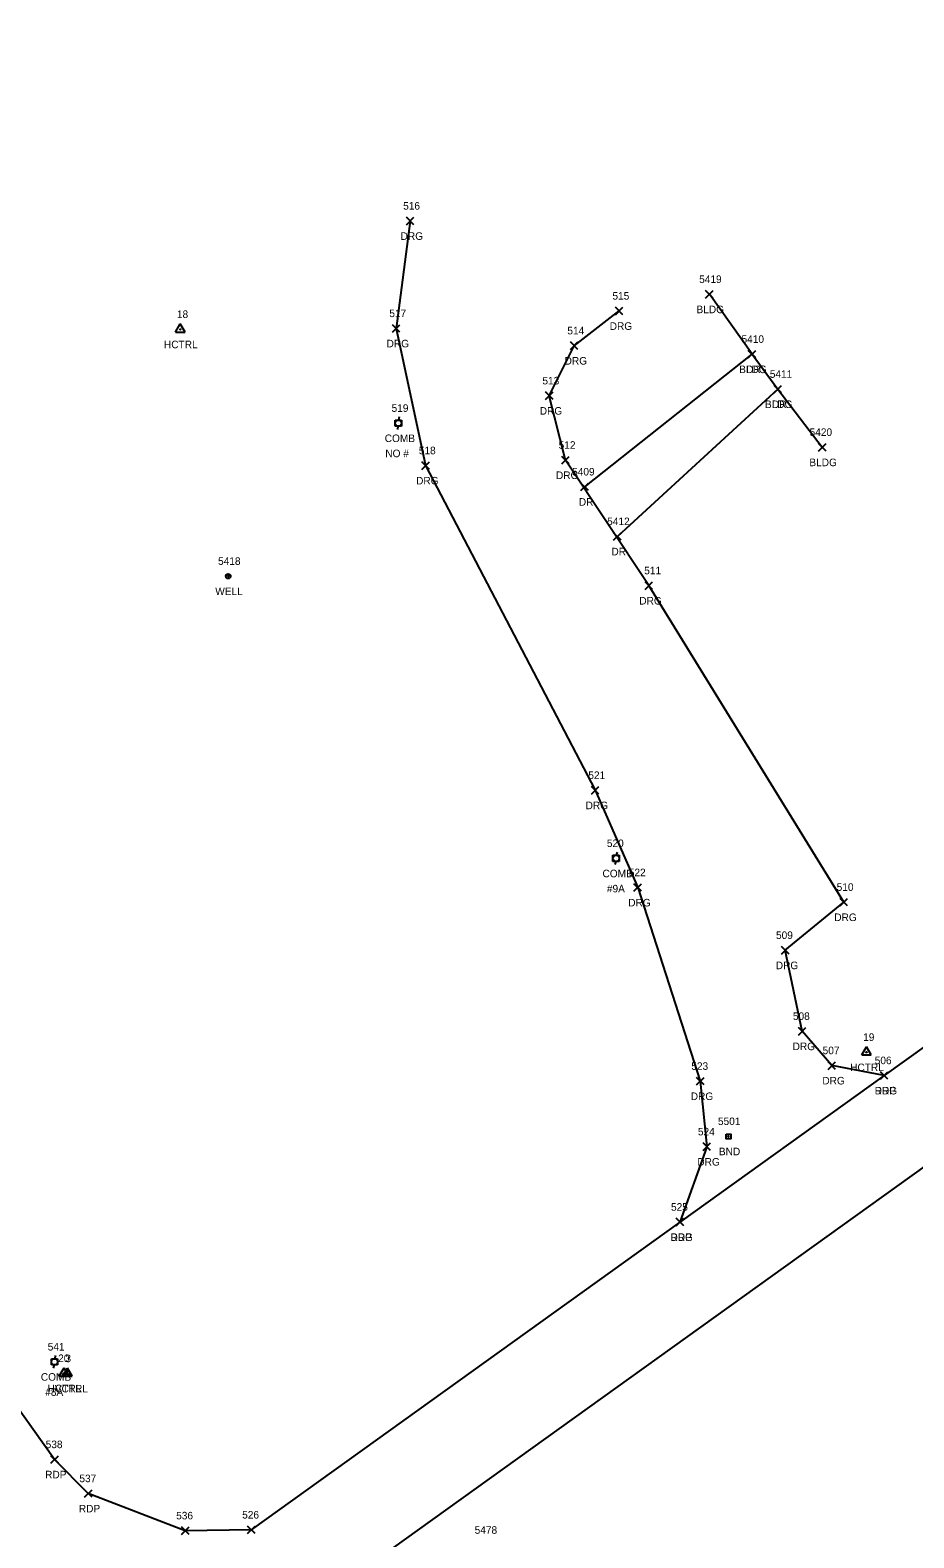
# Model space of a CAD drawing. Extents: x 1481523 to 1489083, y 884156 to 893756.
# Drawn here: x 1487626 to 1487859.9, y 886406.2 to 886805.3 of the extents above; entities that cross this region are included whole.
import ezdxf

# ---------------------------------------------------------------- set-up
doc = ezdxf.new("R2010")
doc.units = 0
for name, color, linetype in [('C_A', 7, 'Continuous'), ('C_I', 7, 'Continuous'), ('CPH', 7, 'Continuous'), ('CPSM', 7, 'Continuous'), ('L_A', 7, 'Continuous'), ('L_I', 7, 'Continuous'), ('L_TIC', 7, 'Continuous'), ('LBC', 7, 'Continuous'), ('Level 18', 7, 'Continuous'), ('M_A', 7, 'Continuous'), ('M_I', 7, 'Continuous'), ('P_A', 7, 'Continuous'), ('P_I', 7, 'Continuous'), ('P_TIC', 7, 'Continuous'), ('PET', 7, 'Continuous'), ('R_A', 7, 'Continuous'), ('R_I', 7, 'Continuous'), ('R_TIC', 7, 'Continuous'), ('RDG', 7, 'Continuous'), ('RDP', 7, 'Continuous'), ('U_A', 7, 'Continuous'), ('U_C', 7, 'Continuous'), ('U_I', 7, 'Continuous'), ('UP', 7, 'Continuous'), ('UWW', 7, 'Continuous')]:
    doc.layers.add(name, color=color, linetype=linetype)

msp = doc.modelspace()

# ---------------------------------------------------------------- linework, layer by layer
at = {"layer": 'CPH'}
for p, q in [((1487664.49, 886725.41), (1487665.74, 886727.57)), ((1487664.49, 886725.41), (1487666.99, 886725.41)), ((1487666.99, 886725.41), (1487665.74, 886727.57)), ((1487665.74, 886726.13), (1487665.74, 886726.13)), ((1487846.13, 886534.02), (1487847.38, 886536.19)), ((1487848.63, 886534.02), (1487847.38, 886536.19)), ((1487846.13, 886534.02), (1487848.63, 886534.02)), ((1487847.38, 886534.74), (1487847.38, 886534.74)), ((1487633.7, 886449.01), (1487634.95, 886451.17)), ((1487633.7, 886449.01), (1487636.2, 886449.01)), ((1487636.2, 886449.01), (1487634.95, 886451.17)), ((1487634.95, 886449.73), (1487634.95, 886449.73))]:
    msp.add_line(p, q, dxfattribs=at)
for centre in [(1487665.74, 886726.13), (1487847.38, 886534.74), (1487634.95, 886449.73)]:
    msp.add_circle(centre, 0.0833, dxfattribs=at)
at = {"layer": 'CPSM'}
for p, q in [((1487634.65, 886448.97), (1487635.9, 886451.13)), ((1487634.65, 886448.97), (1487635.9, 886449.69)), ((1487634.65, 886448.97), (1487637.15, 886448.97)), ((1487637.15, 886448.97), (1487635.9, 886451.13)), ((1487635.9, 886449.69), (1487635.9, 886451.13)), ((1487635.9, 886449.69), (1487635.9, 886449.69)), ((1487635.9, 886449.69), (1487637.15, 886448.97))]:
    msp.add_line(p, q, dxfattribs=at)
at = {"layer": 'L_TIC'}
for points in [[(1487804.78, 886734.41), (1487806.78, 886736.41)], [(1487806.78, 886734.41), (1487804.78, 886736.41)], [(1487816.07, 886718.55), (1487818.07, 886720.55)], [(1487818.07, 886718.55), (1487816.07, 886720.55)], [(1487816.07, 886718.55), (1487818.07, 886720.55)], [(1487818.07, 886718.55), (1487816.07, 886720.55)], [(1487822.91, 886709.3), (1487824.91, 886711.3)], [(1487824.91, 886709.3), (1487822.91, 886711.3)], [(1487834.66, 886693.91), (1487836.66, 886695.91)], [(1487836.66, 886693.91), (1487834.66, 886695.91)]]:
    msp.add_lwpolyline(points, dxfattribs=at)
at = {"layer": 'LBC'}
for points in [[(1487817.07, 886719.55), (1487805.78, 886735.41)], [(1487817.07, 886719.55), (1487823.91, 886710.3), (1487835.66, 886694.91)]]:
    msp.add_lwpolyline(points, dxfattribs=at)
at = {"layer": 'Level 18'}
msp.add_lwpolyline([(1487810.19, 886513.09), (1487811.44, 886513.09), (1487811.44, 886511.84), (1487810.19, 886511.84)], close=True, dxfattribs=at)
msp.add_circle((1487810.82, 886512.47), 0.0833, dxfattribs=at)
at = {"layer": 'P_TIC'}
for points in [[(1487851.05, 886527.58), (1487853.05, 886529.58)], [(1487853.05, 886527.58), (1487851.05, 886529.58)], [(1487796.99, 886488.79), (1487798.99, 886490.79)], [(1487798.99, 886488.79), (1487796.99, 886490.79)], [(1487631.47, 886425.93), (1487633.47, 886427.93)], [(1487633.47, 886425.93), (1487631.47, 886427.93)], [(1487640.38, 886416.92), (1487642.38, 886418.92)], [(1487642.38, 886416.92), (1487640.38, 886418.92)], [(1487666.06, 886407.07), (1487668.06, 886409.07)], [(1487668.06, 886407.07), (1487666.06, 886409.07)], [(1487683.52, 886407.29), (1487685.52, 886409.29)], [(1487685.52, 886407.29), (1487683.52, 886409.29)]]:
    msp.add_lwpolyline(points, dxfattribs=at)
at = {"layer": 'PET'}
for points in [[(1488003.32, 886636.97), (1487852.05, 886528.58), (1487797.99, 886489.79), (1487684.52, 886408.29), (1487667.06, 886408.07), (1487641.38, 886417.92), (1487632.47, 886426.93), (1487529.89, 886571.08), (1487437.28, 886697.66), (1487418.66, 886723.49), (1487368.4, 886792.53), (1487324.38, 886853.98), (1487266.69, 886933.92), (1487190.62, 887040.47), (1487157.21, 887086.8), (1487121.09, 887136.63)], [(1488127.61, 886694.12), (1488018, 886615.33), (1487866.86, 886507.46), (1487699.04, 886387.04), (1487600.74, 886317.32), (1487423.75, 886189.49), (1487335.51, 886126.88)]]:
    msp.add_lwpolyline(points, dxfattribs=at)
at = {"layer": 'R_TIC'}
for points in [[(1487725.57, 886753.83), (1487727.57, 886755.83)], [(1487727.57, 886753.83), (1487725.57, 886755.83)], [(1487780.91, 886730), (1487782.91, 886732)], [(1487782.91, 886730), (1487780.91, 886732)], [(1487721.86, 886725.37), (1487723.86, 886727.37)], [(1487723.86, 886725.37), (1487721.86, 886727.37)], [(1487768.98, 886720.8), (1487770.98, 886722.8)], [(1487770.98, 886720.8), (1487768.98, 886722.8)], [(1487816.07, 886718.55), (1487818.07, 886720.55)], [(1487818.07, 886718.55), (1487816.07, 886720.55)], [(1487762.39, 886707.55), (1487764.39, 886709.55)], [(1487764.39, 886707.55), (1487762.39, 886709.55)], [(1487822.91, 886709.3), (1487824.91, 886711.3)], [(1487824.91, 886709.3), (1487822.91, 886711.3)], [(1487766.69, 886690.51), (1487768.69, 886692.51)], [(1487768.69, 886690.51), (1487766.69, 886692.51)], [(1487729.66, 886689.07), (1487731.66, 886691.07)], [(1487731.66, 886689.07), (1487729.66, 886691.07)], [(1487771.8, 886683.44), (1487773.8, 886685.44)], [(1487773.8, 886683.44), (1487771.8, 886685.44)], [(1487780.42, 886670.3), (1487782.42, 886672.3)], [(1487782.42, 886670.3), (1487780.42, 886672.3)], [(1487788.76, 886657.28), (1487790.76, 886659.28)], [(1487790.76, 886657.28), (1487788.76, 886659.28)], [(1487774.54, 886603.09), (1487776.54, 886605.09)], [(1487776.54, 886603.09), (1487774.54, 886605.09)], [(1487785.82, 886577.35), (1487787.82, 886579.35)], [(1487787.82, 886577.35), (1487785.82, 886579.35)], [(1487840.37, 886573.48), (1487842.37, 886575.48)], [(1487842.37, 886573.48), (1487840.37, 886575.48)], [(1487824.87, 886560.74), (1487826.87, 886562.74)], [(1487826.87, 886560.74), (1487824.87, 886562.74)], [(1487829.33, 886539.3), (1487831.33, 886541.3)], [(1487831.33, 886539.3), (1487829.33, 886541.3)], [(1487837.2, 886530.22), (1487839.2, 886532.22)], [(1487839.2, 886530.22), (1487837.2, 886532.22)], [(1487802.37, 886526.09), (1487804.37, 886528.09)], [(1487804.37, 886526.09), (1487802.37, 886528.09)], [(1487851.05, 886527.58), (1487853.05, 886529.58)], [(1487853.05, 886527.58), (1487851.05, 886529.58)], [(1487804.12, 886508.73), (1487806.12, 886510.73)], [(1487806.12, 886508.73), (1487804.12, 886510.73)], [(1487796.99, 886488.79), (1487798.99, 886490.79)], [(1487798.99, 886488.79), (1487796.99, 886490.79)]]:
    msp.add_lwpolyline(points, dxfattribs=at)
at = {"layer": 'RDG'}
for points in [[(1487726.57, 886754.83), (1487722.86, 886726.37), (1487730.66, 886690.07), (1487775.54, 886604.09), (1487786.82, 886578.35), (1487803.37, 886527.09), (1487805.12, 886509.73), (1487797.99, 886489.79)], [(1487852.05, 886528.58), (1487838.2, 886531.22), (1487830.33, 886540.3), (1487825.87, 886561.74), (1487841.37, 886574.48), (1487789.76, 886658.28), (1487767.69, 886691.51), (1487763.39, 886708.55), (1487769.98, 886721.8), (1487781.91, 886731)]]:
    msp.add_lwpolyline(points, dxfattribs=at)
at = {"layer": 'RDP'}
for points in [[(1487772.8, 886684.44), (1487817.07, 886719.55)], [(1487823.91, 886710.3), (1487781.42, 886671.3)]]:
    msp.add_lwpolyline(points, dxfattribs=at)
at = {"layer": 'UP'}
for p, q in [((1487722.63, 886700.46), (1487722.63, 886702.12)), ((1487722.63, 886702.12), (1487724.29, 886702.12)), ((1487724.29, 886700.46), (1487722.63, 886700.46)), ((1487723.21, 886699.62), (1487723.46, 886700.46)), ((1487723.71, 886702.96), (1487723.46, 886702.12)), ((1487723.46, 886701.29), (1487723.46, 886701.29)), ((1487724.29, 886702.12), (1487724.29, 886700.46)), ((1487780.27, 886585.24), (1487780.27, 886586.91)), ((1487780.27, 886586.91), (1487781.93, 886586.91)), ((1487781.93, 886585.24), (1487780.27, 886585.24)), ((1487780.85, 886584.41), (1487781.1, 886585.24)), ((1487781.35, 886587.74), (1487781.1, 886586.91)), ((1487781.1, 886586.07), (1487781.1, 886586.07)), ((1487781.93, 886586.91), (1487781.93, 886585.24)), ((1487631.6, 886451.95), (1487631.6, 886453.62)), ((1487631.6, 886453.62), (1487633.27, 886453.62)), ((1487632.68, 886454.45), (1487632.43, 886453.62)), ((1487632.43, 886452.78), (1487632.43, 886452.78)), ((1487633.27, 886453.62), (1487633.27, 886451.95)), ((1487633.27, 886451.95), (1487631.6, 886451.95)), ((1487632.18, 886451.12), (1487632.43, 886451.95))]:
    msp.add_line(p, q, dxfattribs=at)
for centre in [(1487723.46, 886701.29), (1487781.1, 886586.07), (1487632.43, 886452.78)]:
    msp.add_circle(centre, 0.833, dxfattribs=at)
at = {"layer": 'UWW'}
for radius in [0.625, 0.0833]:
    msp.add_circle((1487678.42, 886660.78), radius, dxfattribs=at)

# ---------------------------------------------------------------- texts
at = {"layer": 'C_A'}
for s, p in [('HCTRL', (1487661.41, 886721.13)), ('HCTRL', (1487843.05, 886529.74)), ('HVCTRL', (1487630.59, 886444.69)), ('HCTRL', (1487630.62, 886444.73))]:
    msp.add_text(s, height=2, dxfattribs=at).set_placement(p)
at = {"layer": 'C_I'}
for s, p in [('18', (1487664.84, 886729.13)), ('19', (1487846.48, 886537.74)), ('20', (1487633.4, 886452.73)), ('3', (1487635.33, 886452.69))]:
    msp.add_text(s, height=2, dxfattribs=at).set_placement(p)
at = {"layer": 'L_A'}
for p in [(1487802.37, 886730.41), (1487813.66, 886714.55), (1487813.66, 886714.55), (1487820.5, 886705.3), (1487832.25, 886689.91)]:
    msp.add_text('BLDG', height=2, dxfattribs=at).set_placement(p)
at = {"layer": 'L_I'}
for s, p in [('5419', (1487803.08, 886738.41)), ('5410', (1487814.29, 886722.55)), ('5410', (1487814.29, 886722.55)), ('5411', (1487821.78, 886713.3)), ('5420', (1487832.31, 886697.91))]:
    msp.add_text(s, height=2, dxfattribs=at).set_placement(p)
at = {"layer": 'M_A'}
msp.add_text('BND', height=2, dxfattribs=at).set_placement((1487808.31, 886507.47))
at = {"layer": 'M_I'}
for s, p in [('5501', (1487808.05, 886515.47)), ('5478', (1487743.65, 886407.26))]:
    msp.add_text(s, height=2, dxfattribs=at).set_placement(p)
at = {"layer": 'P_A'}
for p in [(1487849.54, 886523.58), (1487795.48, 886484.79), (1487629.95, 886421.93), (1487638.87, 886412.92)]:
    msp.add_text('RDP', height=2, dxfattribs=at).set_placement(p)
at = {"layer": 'P_I'}
for s, p in [('506', (1487849.55, 886531.58)), ('525', (1487795.63, 886492.79)), ('538', (1487630.1, 886429.93)), ('537', (1487639.02, 886420.92)), ('536', (1487664.64, 886411.07)), ('526', (1487682.11, 886411.29))]:
    msp.add_text(s, height=2, dxfattribs=at).set_placement(p)
at = {"layer": 'R_A'}
for s, p in [('DRG', (1487724.06, 886749.83)), ('DRG', (1487779.4, 886726)), ('DRG', (1487720.34, 886721.37)), ('DRG', (1487767.47, 886716.8)), ('DR', (1487815.5, 886714.55)), ('DRG', (1487760.88, 886703.55)), ('DR', (1487822.34, 886705.3)), ('DRG', (1487765.18, 886686.51)), ('DRG', (1487728.15, 886685.07)), ('DR', (1487771.23, 886679.44)), ('DR', (1487779.85, 886666.3)), ('DRG', (1487787.24, 886653.28)), ('DRG', (1487773.03, 886599.09)), ('DRG', (1487784.31, 886573.35)), ('DRG', (1487838.85, 886569.48)), ('DRG', (1487823.36, 886556.74)), ('DRG', (1487827.82, 886535.3)), ('DRG', (1487835.69, 886526.22)), ('DRG', (1487800.85, 886522.09)), ('DRG', (1487849.54, 886523.58)), ('DRG', (1487802.6, 886504.73)), ('DRG', (1487795.48, 886484.79))]:
    msp.add_text(s, height=2, dxfattribs=at).set_placement(p)
at = {"layer": 'R_I'}
for s, p in [('516', (1487724.72, 886757.83)), ('515', (1487780.12, 886734)), ('517', (1487721.06, 886729.37)), ('514', (1487768.19, 886724.8)), ('5410', (1487814.29, 886722.55)), ('513', (1487761.59, 886711.55)), ('5411', (1487821.78, 886713.3)), ('512', (1487765.89, 886694.51)), ('518', (1487728.87, 886693.07)), ('5409', (1487769.45, 886687.44)), ('5412', (1487778.73, 886674.3)), ('511', (1487788.53, 886661.28)), ('521', (1487773.74, 886607.09)), ('522', (1487784.46, 886581.35)), ('510', (1487839.48, 886577.48)), ('509', (1487823.42, 886564.74)), ('508', (1487827.89, 886543.3)), ('507', (1487835.76, 886534.22)), ('523', (1487801, 886530.09)), ('506', (1487849.55, 886531.58)), ('524', (1487802.75, 886512.73)), ('525', (1487795.63, 886492.79))]:
    msp.add_text(s, height=2, dxfattribs=at).set_placement(p)
at = {"layer": 'U_A'}
for s, p in [('COMB', (1487719.85, 886696.29)), ('WELL', (1487674.99, 886655.78)), ('COMB', (1487777.49, 886581.07)), ('COMB', (1487628.82, 886447.78))]:
    msp.add_text(s, height=2, dxfattribs=at).set_placement(p)
at = {"layer": 'U_C'}
for s, p in [('NO #', (1487720, 886692.29)), ('#9A', (1487778.65, 886577.07)), ('#8A', (1487629.98, 886443.78))]:
    msp.add_text(s, height=2, dxfattribs=at).set_placement(p)
at = {"layer": 'U_I'}
for s, p in [('519', (1487721.66, 886704.29)), ('5418', (1487675.73, 886663.78)), ('520', (1487778.65, 886589.07)), ('541', (1487630.64, 886455.78))]:
    msp.add_text(s, height=2, dxfattribs=at).set_placement(p)

doc.saveas('drawing.dxf')
